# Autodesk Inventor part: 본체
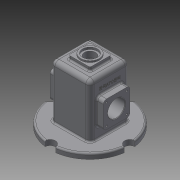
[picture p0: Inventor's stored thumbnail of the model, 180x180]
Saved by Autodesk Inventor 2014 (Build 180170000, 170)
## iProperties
Created: 2018-07
Part Number: 본체
Material: Generic
Document SubType Name: Modeling
Designer: kh
Density: 1 g/cm^3
Appearance: Default
Author: kh
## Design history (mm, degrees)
sketch "스케치1"
  geometry: L1 (37, 55)-(-37, 55); L2 (-37, 55)-(-37, -55); L3 (-37, -55)-(37, -55); L4 (37, -55)-(37, 55); 2 further points
  constraints: 8 end point, 2 parallel, 1 horizontal, 1 midpoint, 1 perpendicular, 1 vertical alignment
  dimensions: "d0" = 74 distance of L2.end L3.end; "d1" = 110 distance of L1.end L2.end; "d2" = 55 distance from line of point (0, 0) L3
extrude "돌출1" new body sketch "스케치1" stored distance "d3" = 74; taper "d4" = 0 deg
fillet "모깎기1" dims "d5" = 8
fillet "모깎기2" dims "d6" = 8
sketch "스케치5"
  geometry: L1 (9, 49)-(49, 49); L2 (49, 49)-(49, 9); L3 (49, 9)-(9, 9); L4 (9, 9)-(9, 49); L5 (9, 49)-(49, 9); L6 (49, 49)-(9, 9); 1 further point
  constraints: 12 end point, 2 midpoint, 2 parallel, 1 horizontal, 1 perpendicular
  dimensions: "d18" = 40 distance of L2.end L3.end; "d19" = 40 distance of L1.end L2.end (= d18)
extrude "돌출4" join sketch "스케치5" distance "d20" = 10; taper "d21" = 0 deg
sketch "스케치6"
  geometry: L1 (49, 49)-(9, 49) reference; L2 (9, 49)-(9, 9) reference; L3 (9, 9)-(49, 9) reference; L4 (49, 9)-(49, 49) reference; C1 r 17.5 at (29, 29); 1 further point
  constraints: 1 centre point, 1 coincident
  dimensions: "d22" = 35 diameter of C1
extrude "돌출5" cut sketch "스케치6" distance "d23" = 3; taper "d24" = 0 deg
node "작업 평면2"
sketch "스케치7"
  geometry: C1 r 14 at (0, 0); C2 r 10.5 at (0, 0); 1 further point
  constraints: 2 centre point, 2 coincident
  dimensions: "d26" = 28 diameter of C1; "d27" = 21 diameter of C2
extrude "돌출6" cut sketch "스케치7" stored distance "d28" = 3; taper "d29" = 0 deg
extrude "돌출7" cut sketch "스케치7" stored distance "d30" = 3; taper "d31" = 0 deg
sketch "스케치8"
  geometry: L1 (0, 0)-(58, 0) reference; L2 (-8, -66)-(-8, -8) reference; L3 (58, -74)-(0, -74) reference; L4 (66, -66)-(66, -8) reference; C1 r 75 at (29, -37); A1 r 8 centre (58, -8) between (66, -8) and (58, 0) reference; A2 r 8 centre (0, -8) between (0, 0) and (-8, -8) reference; A3 r 8 centre (0, -66) between (-8, -66) and (0, -74) reference; A4 r 8 centre (58, -66) between (58, -74) and (66, -66) reference; 1 further point
  constraints: 1 centre point, 1 coincident
  dimensions: "d32" = 150 diameter of C1
extrude "돌출8" join sketch "스케치8" distance "d33" = 10; taper "d34" = 0 deg
fillet "모깎기3" dims "d35" = 3
fillet "모깎기4" dims "d36" = 3
sketch "스케치9"
  geometry: L1 (0, 0)-(-75, 0); C1 r 10 at (-75, 0); 1 further point
  constraints: 2 end point, 1 centre point, 1 coincident, 1 horizontal alignment, 1 other
  dimensions: "d37" = 10 radius of C1
extrude "돌출9" cut sketch "스케치9" stored distance "d38" = 10; taper "d39" = 0 deg
sketch "스케치10"
  geometry: L1 (22, 4)-(72, 4); L2 (72, 4)-(72, 54); L3 (72, 54)-(22, 54); L4 (22, 54)-(22, 4); L5 (22, 4)-(72, 54); L6 (72, 4)-(22, 54); 1 further point
  constraints: 12 end point, 2 midpoint, 2 parallel, 1 horizontal, 1 perpendicular
  dimensions: "d43" = 50 distance of L3.end L2.end; "d44" = 50 distance of L1.end L2.end (= d43)
extrude "돌출10" join sketch "스케치10" distance "d45" = 13; taper "d46" = 0 deg
fillet "모깎기5" dims "d47" = 6
fillet "모깎기6" dims "d48" = 3
node "작업 평면3"
sketch "스케치11"
  geometry: L1 (-3, 61)-(61, 61); L2 (61, 61)-(61, -3); L3 (61, -3)-(-3, -3); L4 (-3, -3)-(-3, 61); L5 (-3, 61)-(61, -3); L6 (61, 61)-(-3, -3); 1 further point
  constraints: 12 end point, 2 midpoint, 2 parallel, 1 horizontal, 1 perpendicular
  dimensions: "d50" = 64 distance of L2.end L3.end; "d51" = 64 distance of L1.end L2.end (= d50)
extrude "돌출11" cut sketch "스케치11" stored distance "d52" = 13; taper "d53" = 0 deg
fillet "모깎기7" dims "d54" = 3
fillet "모깎기8" dims "d55" = 3
node "작업 평면4"
sketch "스케치12"
  geometry: C1 r 25 at (-55, 29); 1 further point
  constraints: 1 centre point, 1 coincident
  dimensions: "d57" = 50 diameter of C1
extrude "돌출12" join sketch "스케치12" stored distance "d58" = 13; taper "d59" = -20 deg
sketch "스케치13"
  geometry: C1 r 16 at (47, 29); 1 further point
  constraints: 1 centre point, 1 coincident
  dimensions: "d60" = 32 diameter of C1
extrude "돌출13" cut sketch "스케치13" stored distance "d61" = 13; taper "d62" = 0 deg
chamfer "모따기1" distance "d63" = 1; stored, may be unused: second distance "d64" = 2, angle "d65" = 45 deg
sketch "스케치14"
  geometry: L1 (66, 54)-(28, 54) reference; L2 (22, 48)-(22, 10) reference; L3 (28, 4)-(66, 4) reference; L4 (72, 10)-(72, 48) reference; C1 r 17 at (47, 29) reference; A1 r 6 centre (66, 48) between (72, 48) and (66, 54) reference; A2 r 6 centre (28, 48) between (28, 54) and (22, 48) reference; A3 r 6 centre (28, 10) between (22, 10) and (28, 4) reference; A4 r 6 centre (66, 10) between (66, 4) and (72, 10) reference; 2 further points
  constraints: 1 coincident
hole "구멍1" sketch "스케치14" at (28, 10) diameter "d66" = 3.242; stored, may be unused: countersink angle "d70" = 90 deg, drill point angle "d72" = 118 deg; dims "d67" = 8, "d68" = 4, "d69" = 2, "d71" = 10
fillet "모깎기9" dims "d77" = 3
fillet "모깎기10" dims "d78" = 3
sketch "스케치15"
  geometry: L1 (-18, 46.5)-(-18, 11.5) reference; L2 (89, 66)-(0, 66) reference; 2 further points
  constraints: 1 other
  dimensions: "d79" = 30 distance from line of L1 point (12, 29); "d80" = 37 distance from line of L2 point (12, 29)
feature "엠보싱1" sketch "스케치15" dims "d18" = 40, "d19" = 40 (= d18), "d81" = 0.5, "d82" = 0
node "솔리드1"
pattern_circular "원형 패턴1" dims angle "d41" = 360 deg
mirror "대칭1"
mirror "대칭2"
pattern_linear "직사각형 패턴1"
mirror "대칭3"
node "투영된 루프2"
node "투영된 루프3"
node "투영된 루프4"
node "투영된 루프5"
other parameters: "d25" = -4, "d49" = -5, "d56" = 7
